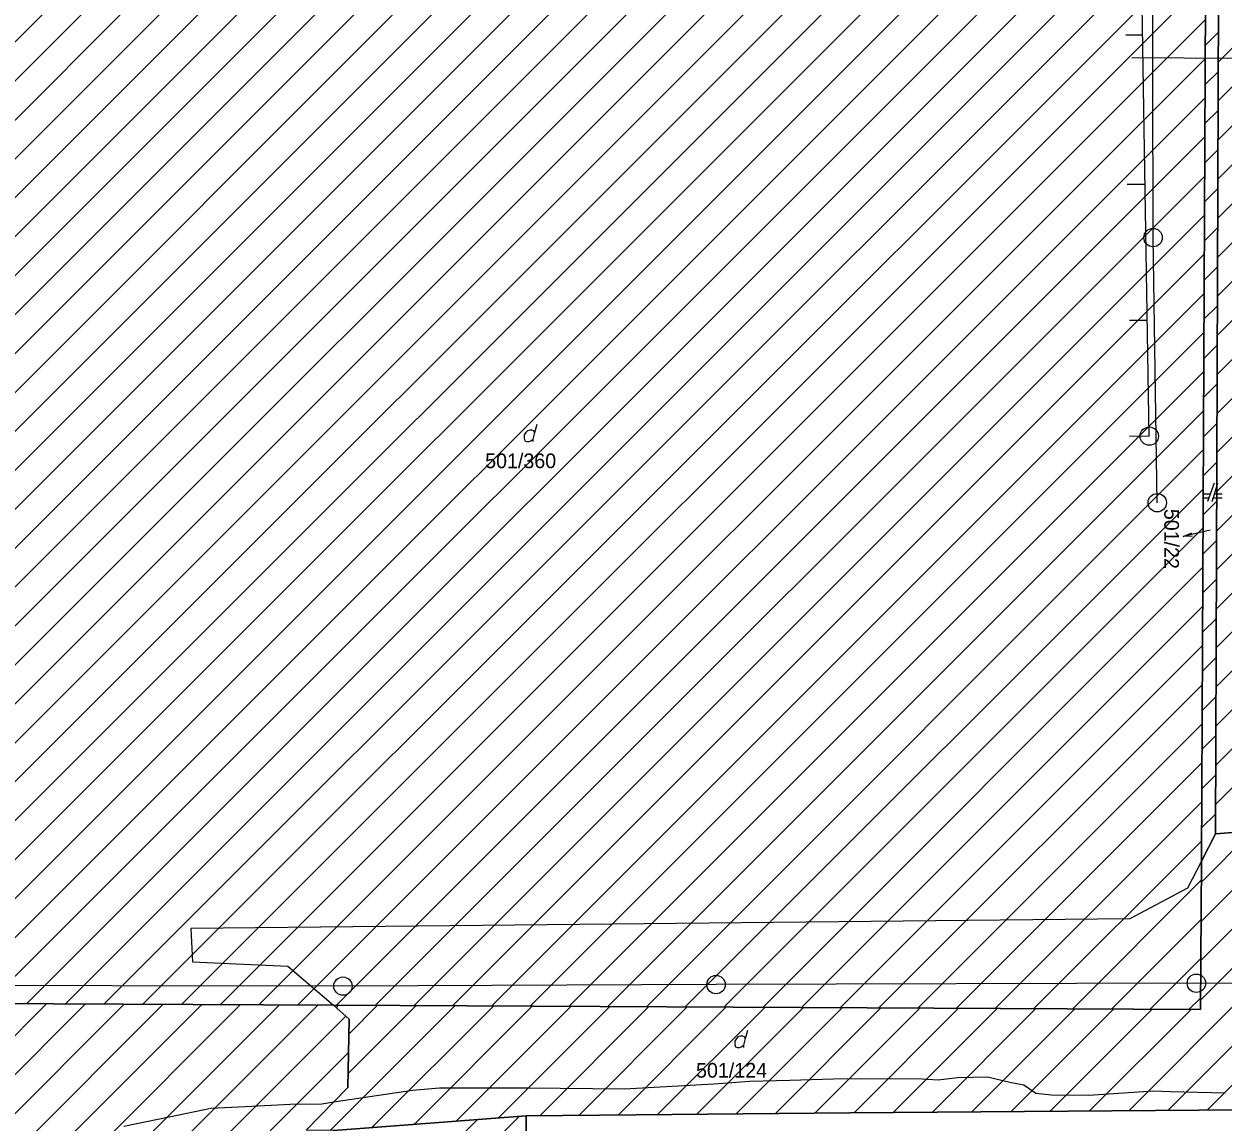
# Model space of a CAD drawing. Extents: x -264309 to -263505, y -1242443 to -1241763.
# Drawn here: x -264079.6 to -263948.8, y -1242319 to -1242199.4 of the extents above; entities that cross this region are included whole.
import ezdxf

# ---------------------------------------------------------------- set-up
doc = ezdxf.new("R2010")
doc.units = 0
for name, color, linetype in [('KFA_DAZDOVA_KANALIZACIA_vetva_D', 7, 'Continuous'), ('KFA_DAZDOVA_KANALIZACIA_vetva_H', 7, 'Continuous'), ('KFA_SO_50-1-II_VODOVODNE_PRIPOJKY', 7, 'Continuous'), ('KFA_SPLASKOVA_KANALIZACIA_SO-40-1-II', 7, 'Continuous'), ('KN_2019_08_16', 7, 'Continuous'), ('KN_2019_08_16_KLADPAR', 7, 'Continuous'), ('KN_2019_08_16_ZAPPAR', 7, 'Continuous'), ('SRAFY_PARCELY', 7, 'Continuous')]:
    doc.layers.add(name, color=color, linetype=linetype)

msp = doc.modelspace()

# ---------------------------------------------------------------- linework, layer by layer
at = {"layer": 'KFA_DAZDOVA_KANALIZACIA_vetva_D'}
msp.add_lwpolyline([(-263821.59, -1242304.45), (-263853.82, -1242304.12), (-263903.79, -1242304.32), (-263951.83, -1242303.9), (-264004.17, -1242304.05), (-264044.82, -1242304.22), (-264095.21, -1242304.15), (-264105.62, -1242304.17)], dxfattribs=at)
for centre in [(-264044.82, -1242304.22), (-264004.17, -1242304.05), (-263951.83, -1242303.9)]:
    msp.add_circle(centre, 1, dxfattribs=at)
at = {"layer": 'KFA_DAZDOVA_KANALIZACIA_vetva_H'}
msp.add_lwpolyline([(-263956.1, -1242251.54), (-263956.55, -1242222.65), (-263956.62, -1242186.72), (-263963.66, -1242184.03)], dxfattribs=at)
for centre in [(-263956.55, -1242222.65), (-263956.1, -1242251.54)]:
    msp.add_circle(centre, 1, dxfattribs=at)
at = {"layer": 'KFA_SO_50-1-II_VODOVODNE_PRIPOJKY'}
msp.add_lwpolyline([(-263924.19, -1242203.3), (-263924.63, -1242203.3), (-263958.87, -1242203.05)], dxfattribs=at)
at = {"layer": 'KFA_SPLASKOVA_KANALIZACIA_SO-40-1-II'}
for p, q in [((-263959.52, -1242200.56), (-263957.69, -1242200.56)), ((-263959.37, -1242216.82), (-263957.42, -1242216.82)), ((-263959.11, -1242231.64), (-263957.18, -1242231.64)), ((-263959.13, -1242244.25), (-263956.97, -1242244.29))]:
    msp.add_line(p, q, dxfattribs=at)
msp.add_lwpolyline([(-263956.97, -1242244.29), (-263957.81, -1242192.95), (-263970.04, -1242192.88)], dxfattribs=at)
msp.add_circle((-263956.97, -1242244.29), 1, dxfattribs=at)
at = {"layer": 'KN_2019_08_16'}
msp.add_lwpolyline([(-264068.7, -1242319.48), (-264063.75, -1242318.45), (-264059.23, -1242317.5), (-264055.45, -1242317.35), (-264050.57, -1242317.07), (-264047.11, -1242317.03), (-264045.81, -1242316.84), (-264037.23, -1242315.56), (-264034.31, -1242315.31), (-264024.65, -1242315.29), (-264014.13, -1242315.41), (-264004.4, -1242314.87), (-264000.5, -1242314.59), (-263996.15, -1242314.45), (-263991.36, -1242314.31), (-263986.12, -1242314.3), (-263981.72, -1242314.33), (-263979.98, -1242314.43), (-263977.86, -1242314.19), (-263974.61, -1242314.09), (-263972.17, -1242314.7), (-263970.63, -1242314.99), (-263969.31, -1242315.89), (-263967.63, -1242316.08), (-263963.59, -1242316.09), (-263956.5, -1242315.61), (-263954.68, -1242315.7), (-263948.7, -1242315.83)], dxfattribs=at)
at = {"layer": 'KN_2019_08_16_KLADPAR'}
for p, q in [((-264023.92, -1242243.89), (-264023.65, -1242242.99)), ((-263949.91, -1242249.42), (-263950.61, -1242251.42)), ((-263950.11, -1242251.42), (-263949.51, -1242249.42)), ((-263950.33, -1242250.62), (-263951.01, -1242250.62)), ((-263949.01, -1242250.62), (-263949.87, -1242250.62)), ((-263951.01, -1242251.02), (-263950.47, -1242251.02)), ((-263949.99, -1242251.02), (-263949.01, -1242251.02)), ((-263952.25, -1242255.2), (-263953.27, -1242255.23)), ((-264000.97, -1242309.93), (-264000.7, -1242309.03))]:
    msp.add_line(p, q, dxfattribs=at)
for points in [[(-263945.92, -1242287.35), (-263949.74, -1242287.63), (-263949.41, -1242196.68), (-263949.38, -1242187.85), (-263949.49, -1242175.05), (-263949.55, -1242159.39), (-263950.14, -1242129.96), (-263950.48, -1242111.43), (-263955.8, -1242087.79), (-263956.24, -1242069.24), (-263949.96, -1242070.83), (-263947.13, -1242072.33), (-263942.68, -1242071.91), (-263941.47, -1242124.08), (-263944.59, -1242125.87), (-263946.11, -1242129.79), (-263945.51, -1242159.3), (-263945.41, -1242187.87)], [(-263950.84, -1242196.76), (-263951.29, -1242290.6), (-263951.37, -1242306.76), (-264045.86, -1242306.31), (-264099.36, -1242306.05), (-264098.84, -1242196.05), (-264070.8, -1242196.19)], [(-263951.29, -1242290.6), (-263950.84, -1242196.76), (-263949.41, -1242196.68), (-263949.74, -1242287.63)], [(-264045.86, -1242306.31), (-263951.37, -1242306.76), (-263951.29, -1242290.6), (-263949.74, -1242287.63), (-263945.92, -1242287.35), (-263946.05, -1242311.56), (-263938.35, -1242311.44), (-263937.4, -1242310.7), (-263937.27, -1242317.62), (-263989.58, -1242318.02), (-264012.87, -1242318.24), (-264024.87, -1242318.35), (-264045.81, -1242319.96), (-264048.82, -1242319.93), (-264044.28, -1242315.26), (-264044.13, -1242307.8)], [(-264045.81, -1242319.96), (-264024.87, -1242318.35), (-264024.64, -1242344.82), (-264045.98, -1242345.11), (-264045.96, -1242342.04)]]:
    msp.add_lwpolyline(points, close=True, dxfattribs=at)
for points in [[(-264024.1, -1242244.88), (-264024.1, -1242244.61), (-264023.92, -1242243.89), (-264024.01, -1242243.71), (-264024.19, -1242243.62), (-264024.46, -1242243.62), (-264024.73, -1242243.71), (-264024.91, -1242243.89), (-264025.09, -1242244.16), (-264025.09, -1242244.52), (-264025, -1242244.79), (-264024.82, -1242244.88), (-264024.55, -1242244.88), (-264024.37, -1242244.79), (-264024.1, -1242244.61)], [(-263950.35, -1242254.55), (-263953.27, -1242255.23), (-263952.34, -1242254.81)], [(-264099.36, -1242306.05), (-264045.86, -1242306.31), (-264044.13, -1242307.8), (-264044.28, -1242315.26), (-264048.82, -1242319.93)], [(-264001.15, -1242310.92), (-264001.15, -1242310.65), (-264000.97, -1242309.93), (-264001.06, -1242309.75), (-264001.24, -1242309.66), (-264001.51, -1242309.66), (-264001.78, -1242309.75), (-264001.96, -1242309.93), (-264002.14, -1242310.2), (-264002.14, -1242310.56), (-264002.05, -1242310.83), (-264001.87, -1242310.92), (-264001.6, -1242310.92), (-264001.42, -1242310.83), (-264001.15, -1242310.65)], [(-264069.25, -1242345.54), (-264061.99, -1242345.41), (-264045.98, -1242345.11), (-264024.64, -1242344.82), (-264024.87, -1242318.35), (-264012.87, -1242318.24), (-263989.58, -1242318.02), (-263937.27, -1242317.62), (-263930.87, -1242317.54), (-263870.55, -1242316.79)]]:
    msp.add_lwpolyline(points, dxfattribs=at)
at = {"layer": 'KN_2019_08_16_ZAPPAR'}
msp.add_line((-263959.09, -1242296.88), (-264061.39, -1242297.92), dxfattribs=at)
for points in [[(-263951.29, -1242290.6), (-263952.82, -1242293.54), (-263959.09, -1242296.88)], [(-264061.39, -1242297.92), (-264061.23, -1242301.58), (-264050.83, -1242302.04), (-264045.86, -1242306.31)]]:
    msp.add_lwpolyline(points, dxfattribs=at)
at = {"layer": 'SRAFY_PARCELY'}
for p, q in [((-264099.35, -1242304.97), (-263990.95, -1242196.57)), ((-264099.33, -1242300.71), (-263995.17, -1242196.55)), ((-264099.31, -1242296.45), (-263999.39, -1242196.53)), ((-264099.29, -1242292.19), (-264003.62, -1242196.51)), ((-264099.27, -1242287.92), (-264007.84, -1242196.49)), ((-264099.25, -1242283.66), (-264012.06, -1242196.47)), ((-264099.23, -1242279.4), (-264016.29, -1242196.45)), ((-264099.21, -1242275.14), (-264020.51, -1242196.43)), ((-264099.19, -1242270.87), (-264024.73, -1242196.41)), ((-264099.17, -1242266.61), (-264028.95, -1242196.39)), ((-264099.15, -1242262.35), (-264033.18, -1242196.37)), ((-264099.13, -1242258.08), (-264037.4, -1242196.35)), ((-264099.11, -1242253.82), (-264041.62, -1242196.33)), ((-264099.09, -1242249.56), (-264045.84, -1242196.31)), ((-264099.07, -1242245.3), (-264050.07, -1242196.29)), ((-264099.05, -1242241.03), (-264054.29, -1242196.27)), ((-264099.03, -1242236.77), (-264058.51, -1242196.25)), ((-264099.01, -1242232.51), (-264062.73, -1242196.23)), ((-264098.99, -1242228.24), (-264066.96, -1242196.21)), ((-264098.97, -1242223.98), (-264071.18, -1242196.19)), ((-264098.95, -1242219.72), (-264075.4, -1242196.17)), ((-264096.2, -1242306.07), (-263986.73, -1242196.59)), ((-264091.98, -1242306.09), (-263982.5, -1242196.61)), ((-264087.76, -1242306.11), (-263978.28, -1242196.63)), ((-264083.54, -1242306.13), (-263974.06, -1242196.65)), ((-264079.31, -1242306.15), (-263969.84, -1242196.67)), ((-264075.09, -1242306.17), (-263965.61, -1242196.69)), ((-264070.87, -1242306.19), (-263961.39, -1242196.71)), ((-264066.65, -1242306.21), (-263957.17, -1242196.73)), ((-264062.43, -1242306.23), (-263952.95, -1242196.75)), ((-264058.2, -1242306.25), (-263950.85, -1242198.9)), ((-263949.43, -1242203.49), (-263945.47, -1242199.53)), ((-263950.86, -1242201.72), (-263949.42, -1242200.28)), ((-264053.98, -1242306.27), (-263950.87, -1242203.16)), ((-263949.45, -1242207.75), (-263945.49, -1242203.79)), ((-263950.88, -1242205.98), (-263949.44, -1242204.54)), ((-264049.76, -1242306.29), (-263950.89, -1242207.42)), ((-263950.9, -1242210.24), (-263949.45, -1242208.79)), ((-263949.47, -1242212.01), (-263945.51, -1242208.06)), ((-264045.54, -1242306.31), (-263950.91, -1242211.69)), ((-263949.48, -1242216.27), (-263945.54, -1242212.32)), ((-263950.93, -1242214.51), (-263949.47, -1242213.05)), ((-264041.31, -1242306.33), (-263950.93, -1242215.95)), ((-263949.5, -1242220.52), (-263945.56, -1242216.58)), ((-263950.95, -1242218.77), (-263949.48, -1242217.31)), ((-264037.09, -1242306.35), (-263950.95, -1242220.21)), ((-263949.51, -1242224.78), (-263945.58, -1242220.85)), ((-263950.97, -1242223.03), (-263949.5, -1242221.57)), ((-264032.87, -1242306.37), (-263950.97, -1242224.47)), ((-263950.99, -1242227.3), (-263949.52, -1242225.83)), ((-263949.53, -1242229.04), (-263945.6, -1242225.11)), ((-264028.65, -1242306.39), (-263950.99, -1242228.74)), ((-263949.54, -1242233.3), (-263945.62, -1242229.38)), ((-263951.01, -1242231.56), (-263949.53, -1242230.08)), ((-264024.42, -1242306.41), (-263951.01, -1242233)), ((-263949.56, -1242237.56), (-263945.64, -1242233.64)), ((-263951.03, -1242235.82), (-263949.55, -1242234.34)), ((-264020.2, -1242306.43), (-263951.03, -1242237.26)), ((-263951.05, -1242240.09), (-263949.56, -1242238.6)), ((-263949.57, -1242241.81), (-263945.67, -1242237.91)), ((-264015.98, -1242306.45), (-263951.05, -1242241.53)), ((-263951.07, -1242244.35), (-263949.58, -1242242.86)), ((-263949.59, -1242246.07), (-263945.69, -1242242.17)), ((-264011.76, -1242306.47), (-263951.08, -1242245.79)), ((-263949.6, -1242250.33), (-263945.71, -1242246.44)), ((-263951.09, -1242248.61), (-263949.59, -1242247.12)), ((-264007.53, -1242306.49), (-263951.1, -1242250.05)), ((-263949.62, -1242254.59), (-263945.73, -1242250.7)), ((-263951.11, -1242252.88), (-263949.61, -1242251.38)), ((-264003.31, -1242306.51), (-263951.12, -1242254.32)), ((-263951.13, -1242257.14), (-263949.62, -1242255.63)), ((-263949.64, -1242258.85), (-263945.75, -1242254.96)), ((-263999.09, -1242306.53), (-263951.14, -1242258.58)), ((-263951.15, -1242261.4), (-263949.64, -1242259.89)), ((-263949.65, -1242263.1), (-263945.78, -1242259.23)), ((-263994.87, -1242306.55), (-263951.16, -1242262.84)), ((-263949.67, -1242267.36), (-263945.8, -1242263.49)), ((-263951.17, -1242265.66), (-263949.65, -1242264.15)), ((-263990.64, -1242306.57), (-263951.18, -1242267.11)), ((-263949.68, -1242271.62), (-263945.82, -1242267.76)), ((-263951.19, -1242269.93), (-263949.67, -1242268.41)), ((-263986.42, -1242306.59), (-263951.2, -1242271.37)), ((-263951.21, -1242274.19), (-263949.69, -1242272.67)), ((-263949.7, -1242275.88), (-263945.84, -1242272.02)), ((-263982.2, -1242306.61), (-263951.22, -1242275.63)), ((-263951.23, -1242278.45), (-263949.7, -1242276.92)), ((-263949.71, -1242280.14), (-263945.86, -1242276.29)), ((-263977.98, -1242306.63), (-263951.24, -1242279.9)), ((-263949.73, -1242284.4), (-263945.89, -1242280.55)), ((-263951.25, -1242282.72), (-263949.72, -1242281.18)), ((-263973.75, -1242306.65), (-263951.26, -1242284.16)), ((-263951.27, -1242286.98), (-263949.73, -1242285.44)), ((-263951.3, -1242292.91), (-263945.92, -1242287.53)), ((-263969.53, -1242306.67), (-263951.28, -1242288.42)), ((-263965.31, -1242306.69), (-263951.3, -1242292.68)), ((-263951.32, -1242297.18), (-263945.94, -1242291.8)), ((-263951.34, -1242301.44), (-263945.97, -1242296.06)), ((-263961.09, -1242306.71), (-263951.32, -1242296.95)), ((-263951.36, -1242305.7), (-263945.99, -1242300.33)), ((-263956.86, -1242306.73), (-263951.34, -1242301.21)), ((-263959.21, -1242317.79), (-263946.01, -1242304.59)), ((-263952.64, -1242306.75), (-263951.36, -1242305.48)), ((-264164.19, -1242393.23), (-264077.12, -1242306.16)), ((-264161.94, -1242395.22), (-264072.9, -1242306.18)), ((-264159.68, -1242397.2), (-264068.67, -1242306.2)), ((-264157.42, -1242399.19), (-264064.45, -1242306.22)), ((-264155.16, -1242401.17), (-264060.23, -1242306.24)), ((-264111.2, -1242361.45), (-264056.01, -1242306.26)), ((-264092.67, -1242347.16), (-264051.79, -1242306.28)), ((-264061.4, -1242320.13), (-264047.56, -1242306.3)), ((-264046.23, -1242319.96), (-264032.64, -1242306.37)), ((-264045.56, -1242306.57), (-264045.31, -1242306.31)), ((-264044.25, -1242313.74), (-264036.87, -1242306.35)), ((-264044.16, -1242309.41), (-264041.09, -1242306.33)), ((-264041.67, -1242319.64), (-264028.42, -1242306.39)), ((-264037.07, -1242319.29), (-264024.2, -1242306.41)), ((-264032.48, -1242318.93), (-264019.98, -1242306.43)), ((-264027.88, -1242318.58), (-264015.75, -1242306.45)), ((-264023.39, -1242318.34), (-264011.53, -1242306.47)), ((-264019.11, -1242318.3), (-264007.31, -1242306.49)), ((-264014.83, -1242318.26), (-264003.09, -1242306.51)), ((-264010.55, -1242318.22), (-263998.86, -1242306.53)), ((-264006.26, -1242318.18), (-263994.64, -1242306.55)), ((-264001.98, -1242318.14), (-263990.42, -1242306.57)), ((-263997.7, -1242318.1), (-263986.2, -1242306.59)), ((-263993.42, -1242318.06), (-263981.97, -1242306.61)), ((-263989.13, -1242318.02), (-263977.75, -1242306.63)), ((-263984.86, -1242317.98), (-263973.53, -1242306.65)), ((-263980.58, -1242317.95), (-263969.31, -1242306.67)), ((-263976.31, -1242317.92), (-263965.08, -1242306.69)), ((-263972.03, -1242317.89), (-263960.86, -1242306.71)), ((-263967.76, -1242317.85), (-263956.64, -1242306.73)), ((-263963.48, -1242317.82), (-263952.42, -1242306.76)), ((-264057.08, -1242320.06), (-264044.5, -1242307.48)), ((-263954.93, -1242317.76), (-263946.04, -1242308.86)), ((-264052.77, -1242319.99), (-264044.2, -1242311.43)), ((-263950.65, -1242317.72), (-263944.47, -1242311.54)), ((-264045.94, -1242338.77), (-264025.57, -1242318.4)), ((-264045.91, -1242334.5), (-264030.17, -1242318.76))]:
    msp.add_line(p, q, dxfattribs=at)

# ---------------------------------------------------------------- texts
at = {"layer": 'KN_2019_08_16_KLADPAR'}
for s, p in [('501/360', (-264029.33, -1242247.78)), ('501/124', (-264006.35, -1242314.19))]:
    msp.add_text(s, height=1.6, dxfattribs=at).set_placement(p)
msp.add_text('501/22', height=1.6, rotation=269.9777, dxfattribs=at).set_placement((-263955.33, -1242252.21))

doc.saveas('drawing.dxf')
